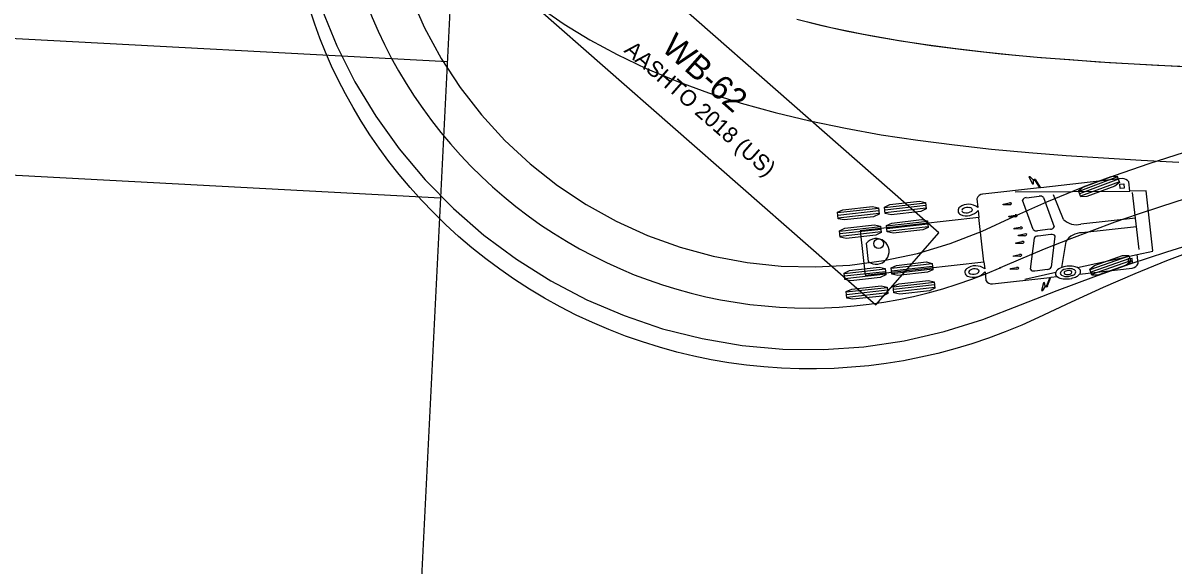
# Model space of a CAD drawing. Extents: x 260275 to 261282, y 610916 to 614143.
# Drawn here: x 260983.2 to 261085.2, y 611559.8 to 611607.9 of the extents above; entities that cross this region are included whole.
import ezdxf

# ---------------------------------------------------------------- set-up
doc = ezdxf.new("R2010")
doc.units = 0
for name, color, linetype in [('DR_P_Ditch', 7, 'Continuous'), ('GE_X_Alignment', 7, 'Continuous'), ('UT_X_Water_Cells', 7, 'Continuous')]:
    doc.layers.add(name, color=color, linetype=linetype)

msp = doc.modelspace()

# ---------------------------------------------------------------- linework, layer by layer
at = {"layer": 'DR_P_Ditch'}
for p, q in [((260829.51, 611614.68), (261020.82, 611604.53)), ((260828.86, 611602.6), (261020.18, 611592.44))]:
    msp.add_line(p, q, dxfattribs=at)
at = {"layer": 'GE_X_Alignment'}
msp.add_line((260986.25, 610915.95), (261148.28, 614142.84), dxfattribs=at)
at = {"layer": 'UT_X_Water_Cells'}
for p, q in [((261072.76, 611594.02), (261072.75, 611594.03)), ((261072.77, 611593.99), (261072.76, 611594.02)), ((261080.22, 611594.28), (261076.79, 611593)), ((261080.31, 611594.07), (261076.87, 611592.78)), ((261071.14, 611592.97), (261081.33, 611593.03)), ((261080.39, 611593.85), (261076.95, 611592.57)), ((261080.43, 611593.63), (261080.78, 611593.67)), ((261080.47, 611593.25), (261080.43, 611593.63)), ((261080.82, 611593.29), (261080.47, 611593.25)), ((261080.78, 611593.67), (261080.82, 611593.29)), ((261082.14, 611587.84), (261081.57, 611592.91)), ((261083.36, 611587.71), (261082.77, 611593.04)), ((261063.2, 611591.96), (261059.56, 611591.55)), ((261067.75, 611592.34), (261067.84, 611591.57)), ((261070.09, 611591.87), (261070.64, 611591.97)), ((261070.1, 611591.79), (261070.09, 611591.87)), ((261072.75, 611589.62), (261071.81, 611592.22)), ((261072.16, 611592.44), (261073.28, 611592.57)), ((261073.67, 611592.46), (261074.61, 611589.85)), ((261075.43, 611590.51), (261074.55, 611592.69)), ((261059.03, 611591.49), (261055.38, 611591.08)), ((261059.05, 611591.26), (261055.41, 611590.86)), ((261059.08, 611591.04), (261055.43, 611590.63)), ((261063.23, 611591.73), (261059.58, 611591.32)), ((261063.25, 611591.5), (261059.61, 611591.09)), ((261070.65, 611591.81), (261070.1, 611591.79)), ((261070.6, 611590.8), (261071.17, 611590.9)), ((261059.21, 611589.85), (261055.57, 611589.44)), ((261063.38, 611590.32), (261059.74, 611589.91)), ((261063.41, 611590.09), (261059.77, 611589.68)), ((261063.43, 611589.86), (261059.79, 611589.45)), ((261068.38, 611586.74), (261067.94, 611590.69)), ((261070.61, 611590.72), (261070.6, 611590.8)), ((261071.18, 611590.75), (261070.61, 611590.72)), ((261071.06, 611589.73), (261071.6, 611589.83)), ((261081.83, 611590.62), (261076.97, 611590.08)), ((261081.91, 611589.86), (261077.05, 611589.32)), ((261059.24, 611589.62), (261055.59, 611589.22)), ((261059.26, 611589.4), (261055.62, 611588.99)), ((261071.07, 611589.65), (261071.06, 611589.73)), ((261071.62, 611589.67), (261071.07, 611589.65)), ((261071.43, 611589.12), (261071.98, 611589.22)), ((261071.44, 611589.04), (261071.43, 611589.12)), ((261071.99, 611589.06), (261071.44, 611589.04)), ((261072.84, 611588.84), (261072.49, 611586.09)), ((261074.26, 611589.63), (261073.14, 611589.51)), ((261074.31, 611589.16), (261073.19, 611589.03)), ((261074.36, 611586.27), (261074.7, 611589.02)), ((261057.93, 611588.39), (261058.11, 611586.78)), ((261071.2, 611588.44), (261071.74, 611588.54)), ((261071.21, 611588.36), (261071.2, 611588.44)), ((261071.76, 611588.38), (261071.21, 611588.36)), ((261075.65, 611588.56), (261075.27, 611586.23)), ((261070.99, 611587.29), (261071.53, 611587.39)), ((261071, 611587.21), (261070.99, 611587.29)), ((261071.55, 611587.24), (261071, 611587.21)), ((261076.67, 611586.24), (261081.96, 611587.4)), ((261081.24, 611587.26), (261077.78, 611586.04)), ((261081.31, 611587.05), (261077.86, 611585.82)), ((261081.39, 611586.83), (261077.93, 611585.61)), ((261081.52, 611587.04), (261081.17, 611587)), ((261081.17, 611587), (261081.21, 611586.62)), ((261081.56, 611586.66), (261081.52, 611587.04)), ((261059.63, 611586.09), (261055.98, 611585.68)), ((261059.65, 611585.86), (261056.01, 611585.46)), ((261063.8, 611586.56), (261060.16, 611586.15)), ((261063.83, 611586.33), (261060.18, 611585.92)), ((261063.85, 611586.1), (261060.21, 611585.69)), ((261068.48, 611585.86), (261068.56, 611585.09)), ((261070.73, 611586.14), (261071.27, 611586.24)), ((261070.74, 611586.06), (261070.73, 611586.14)), ((261071.29, 611586.08), (261070.74, 611586.06)), ((261072.01, 611585.22), (261074.75, 611585.82)), ((261072.88, 611585.95), (261074.01, 611586.08)), ((261076.86, 611585.66), (261081.54, 611586.18)), ((261081.21, 611586.62), (261081.56, 611586.66)), ((261059.68, 611585.64), (261056.04, 611585.23)), ((261063.99, 611584.92), (261060.34, 611584.51)), ((261059.81, 611584.45), (261056.17, 611584.04)), ((261059.84, 611584.22), (261056.19, 611583.82)), ((261059.86, 611584), (261056.22, 611583.59)), ((261064.01, 611584.69), (261060.37, 611584.28)), ((261064.04, 611584.46), (261060.39, 611584.05)), ((261073.82, 611584.55), (261073.8, 611584.53)), ((261073.81, 611584.58), (261073.82, 611584.55))]:
    msp.add_line(p, q, dxfattribs=at)
for points in [[(261022.79, 611614.58), (261022.78, 611614.56), (261058.78, 611582.93), (261061.59, 611586.12), (261064.39, 611589.32), (261028.39, 611620.95), (261028.37, 611620.93)], [(261017.52, 611610.37), (261018.77, 611607.52), (261020.25, 611604.8), (261021.93, 611602.22), (261023.82, 611599.78), (261025.9, 611597.52), (261028.15, 611595.43), (261030.55, 611593.53), (261033.1, 611591.84), (261035.77, 611590.36), (261038.55, 611589.09), (261041.43, 611588.06), (261044.37, 611587.26), (261047.37, 611586.69), (261050.4, 611586.37), (261053.44, 611586.29), (261056.48, 611586.45), (261059.5, 611586.85), (261062.48, 611587.49), (261065.39, 611588.37), (261068.23, 611589.47), (261071.04, 611590.78), (261073.95, 611592.07), (261076.92, 611593.28), (261079.95, 611594.41), (261083.03, 611595.47), (261086.16, 611596.47)], [(261029.01, 611609.32), (261031.15, 611607.85), (261033.43, 611606.45), (261035.86, 611605.14), (261038.43, 611603.92), (261041.13, 611602.79), (261043.95, 611601.76), (261046.86, 611600.83), (261049.87, 611599.99), (261052.95, 611599.25), (261056.09, 611598.6), (261059.28, 611598.03), (261062.51, 611597.54), (261065.77, 611597.12), (261069.06, 611596.76), (261072.36, 611596.45), (261075.67, 611596.19), (261078.99, 611595.97), (261082.33, 611595.77), (261085.66, 611595.6)], [(261087.32, 611587.86), (261084.56, 611586.82), (261081.77, 611585.69), (261078.96, 611584.47), (261076.11, 611583.17), (261073.21, 611581.79), (261071.74, 611581.13), (261070.27, 611580.52), (261068.79, 611579.97), (261067.3, 611579.46), (261065.8, 611579.01), (261064.29, 611578.62), (261062.77, 611578.27), (261061.25, 611577.97), (261059.72, 611577.72), (261058.18, 611577.52), (261056.64, 611577.38), (261055.09, 611577.28), (261053.53, 611577.24), (261051.98, 611577.24), (261050.42, 611577.3), (261048.86, 611577.41), (261047.31, 611577.57), (261045.75, 611577.78), (261044.2, 611578.05), (261042.66, 611578.37), (261041.13, 611578.73), (261039.6, 611579.16), (261038.09, 611579.63), (261036.6, 611580.15), (261035.12, 611580.73), (261033.66, 611581.35), (261032.22, 611582.02), (261030.81, 611582.74), (261029.42, 611583.51), (261028.07, 611584.32), (261026.74, 611585.18), (261025.45, 611586.08), (261024.19, 611587.01), (261022.97, 611587.99), (261021.79, 611589), (261020.65, 611590.04), (261019.55, 611591.11), (261018.5, 611592.21), (261017.49, 611593.34), (261016.53, 611594.49), (261015.61, 611595.65), (261014.75, 611596.83), (261013.92, 611598.03), (261013.15, 611599.24), (261012.43, 611600.45), (261011.75, 611601.67), (261011.12, 611602.89), (261010.53, 611604.12), (261009.99, 611605.36), (261009.49, 611606.59), (261009.03, 611607.83), (261008.61, 611609.07)], [(261009.66, 611609.18), (261011, 611605.91), (261012.6, 611602.73), (261014.44, 611599.68), (261016.52, 611596.78), (261018.82, 611594.03), (261021.33, 611591.47), (261024.03, 611589.11), (261026.92, 611586.97), (261029.96, 611585.05), (261033.15, 611583.38), (261036.46, 611581.97), (261039.88, 611580.81), (261043.38, 611579.93), (261046.93, 611579.32), (261050.53, 611579), (261054.14, 611578.96), (261057.74, 611579.21), (261061.32, 611579.74), (261064.84, 611580.55), (261068.28, 611581.64), (261071.61, 611582.94), (261074.87, 611584.21), (261078.12, 611585.42), (261081.35, 611586.57), (261084.59, 611587.64), (261087.81, 611588.65)], [(261051.78, 611608.28), (261054, 611607.73), (261056.28, 611607.23), (261058.62, 611606.77), (261061, 611606.36), (261063.42, 611606), (261065.88, 611605.67), (261068.37, 611605.38), (261070.88, 611605.12), (261073.42, 611604.89), (261075.99, 611604.69), (261078.57, 611604.51), (261083.78, 611604.21), (261089.04, 611603.96)], [(261052.01, 611608.22), (261054.81, 611607.54), (261057.7, 611606.94), (261060.67, 611606.42), (261063.7, 611605.96), (261066.78, 611605.56), (261069.92, 611605.21), (261073.09, 611604.92), (261076.29, 611604.67), (261079.53, 611604.45), (261082.79, 611604.26), (261086.07, 611604.09)], [(261072.89, 611593.99), (261072.89, 611593.99), (261073.32, 611593.31), (261068.27, 611592.75)], [(261072.83, 611594.04), (261072.75, 611594.03), (261072.47, 611594.3), (261072.35, 611594.29), (261072.68, 611593.66), (261072.79, 611593.67), (261072.77, 611593.99), (261072.85, 611594)], [(261080.65, 611594.13), (261073.42, 611593.32), (261072.97, 611594.02)], [(261083.36, 611587.71), (261082.77, 611593.04), (261081.33, 611593.03), (261081.24, 611593.84)], [(261067.87, 611591.31), (261067.94, 611590.69), (261057.4, 611589.51), (261057.84, 611585.57), (261068.38, 611586.74), (261068.45, 611586.11)], [(261082.05, 611586.59), (261081.96, 611587.4), (261083.35, 611587.7)], [(261069.15, 611584.8), (261074.21, 611585.36), (261073.93, 611584.61), (261073.93, 611584.61)], [(261073.9, 611584.59), (261073.81, 611584.58), (261073.76, 611584.9), (261073.66, 611584.89), (261073.48, 611584.2), (261073.6, 611584.21), (261073.8, 611584.53), (261073.89, 611584.54)], [(261074.02, 611584.6), (261074.3, 611585.37), (261074.87, 611585.44)]]:
    msp.add_lwpolyline(points, dxfattribs=at)
for points in [[(261080.21, 611594.34), (261080.41, 611593.8), (261079.98, 611593.46), (261077.51, 611592.53), (261076.97, 611592.51), (261076.77, 611593.05), (261077.19, 611593.39), (261079.66, 611594.32)], [(261063.2, 611592.01), (261063.26, 611591.44), (261062.77, 611591.22), (261060.14, 611590.92), (261059.61, 611591.04), (261059.55, 611591.61), (261060.04, 611591.83), (261062.67, 611592.13)], [(261059.02, 611591.55), (261059.08, 611590.98), (261058.59, 611590.75), (261055.97, 611590.46), (261055.44, 611590.57), (261055.38, 611591.14), (261055.87, 611591.37), (261058.49, 611591.66)], [(261059.2, 611589.91), (261059.27, 611589.34), (261058.78, 611589.11), (261056.15, 611588.82), (261055.62, 611588.93), (261055.56, 611589.5), (261056.05, 611589.73), (261058.67, 611590.02)], [(261063.38, 611590.37), (261063.44, 611589.8), (261062.95, 611589.58), (261060.33, 611589.28), (261059.8, 611589.4), (261059.73, 611589.97), (261060.22, 611590.19), (261062.85, 611590.49)], [(261081.22, 611587.32), (261081.41, 611586.78), (261080.98, 611586.44), (261078.49, 611585.56), (261077.95, 611585.55), (261077.76, 611586.09), (261078.19, 611586.43), (261080.68, 611587.31)], [(261059.62, 611586.15), (261059.69, 611585.58), (261059.19, 611585.35), (261056.57, 611585.06), (261056.04, 611585.17), (261055.98, 611585.74), (261056.47, 611585.97), (261059.09, 611586.26)], [(261063.8, 611586.61), (261063.86, 611586.04), (261063.37, 611585.82), (261060.75, 611585.52), (261060.22, 611585.64), (261060.15, 611586.21), (261060.64, 611586.43), (261063.27, 611586.73)], [(261063.98, 611584.97), (261064.04, 611584.4), (261063.55, 611584.18), (261060.93, 611583.88), (261060.4, 611584), (261060.34, 611584.57), (261060.83, 611584.79), (261063.45, 611585.09)], [(261059.81, 611584.51), (261059.87, 611583.94), (261059.38, 611583.71), (261056.75, 611583.42), (261056.22, 611583.53), (261056.16, 611584.1), (261056.65, 611584.33), (261059.28, 611584.62)]]:
    msp.add_lwpolyline(points, close=True, dxfattribs=at)
for centre, radius in [((261059.04, 611588.36), 0.424), ((261069.82, 611586.21), 0.0417), ((261069.82, 611586.21), 0.0417)]:
    msp.add_circle(centre, radius, dxfattribs=at)
for centre, radius, start, end in [((261052.87, 611624.64), 42, 177.1255, 293.7992), ((261130.35, 611448.96), 150, 87.0825, 113.7992), ((261072.91, 611593.94), 0.127, 64.2517, 128.4608), ((261072.89, 611594.1), 0.11, 249.3037, 269.4121), ((261072.96, 611594.04), 0.0244, 307.2238, 60.5382), ((261080.63, 611593.34), 0.792, 39.6673, 88.8228), ((261068.3, 611592.18), 0.571, 93.2716, 163.6632), ((261070.7, 611591.79), 0.192, 41.4319, 108.9065), ((261070.67, 611592.01), 0.192, 263.7786, 331.3079), ((261072.12, 611592.11), 0.334, 87.4934, 160.0914), ((261073.38, 611592.18), 0.403, 44.3559, 103.8139), ((261066.47, 611591.29), 0.387, 127.8518, 244.8607), ((261067.02, 611590.51), 1.34, 52.3917, 125.9465), ((261066.83, 611592.17), 1.34, 246.766, 320.3208), ((261066.65, 611591.27), 0.228, 113.6585, 175.5534), ((261066.66, 611591.37), 0.262, 200.1482, 266.6734), ((261066.96, 611590.71), 0.86, 77.9222, 117.8916), ((261066.81, 611591.98), 0.879, 259.2241, 293.8194), ((261067.09, 611591.27), 0.29, 24.0005, 80.1605), ((261067.11, 611591.41), 0.247, 284.7598, 354.6389), ((261071.2, 611590.72), 0.192, 41.4319, 108.9065), ((261071.18, 611590.94), 0.192, 263.7786, 331.3079), ((261071.66, 611589.64), 0.192, 41.4319, 108.9065), ((261074.29, 611589.98), 0.342, 267.958, 337.8845), ((261076.58, 611591.67), 1.63, 225.0321, 283.6228), ((261058.83, 611587.67), 1.14, 231.3562, 141.3562), ((261071.64, 611589.86), 0.192, 263.7786, 331.3079), ((261072.04, 611589.03), 0.192, 41.4319, 108.9065), ((261072.01, 611589.25), 0.192, 263.806, 331.2805), ((261073.04, 611589.89), 0.397, 224.1174, 282.2804), ((261073.18, 611588.64), 0.397, 90.4321, 148.5951), ((261074.42, 611588.83), 0.342, 34.8279, 104.7544), ((261077.03, 611587.69), 1.63, 89.0897, 147.6804), ((261071.8, 611588.36), 0.192, 41.4046, 108.9338), ((261071.78, 611588.58), 0.192, 263.806, 331.2805), ((261071.6, 611587.21), 0.192, 41.4046, 108.9338), ((261071.57, 611587.43), 0.192, 263.806, 331.2805), ((261067.07, 611585.83), 0.383, 126.827, 245.8855), ((261067.63, 611585.05), 1.34, 52.3917, 125.9465), ((261067.44, 611586.71), 1.34, 246.766, 320.3208), ((261067.29, 611585.79), 0.262, 106.0391, 172.5643), ((261067.24, 611585.89), 0.228, 197.1591, 259.0539), ((261067.56, 611585.24), 0.879, 78.8931, 113.4883), ((261067.72, 611585.85), 0.247, 18.0735, 87.9526), ((261067.68, 611585.99), 0.29, 292.5519, 348.712), ((261071.34, 611586.06), 0.192, 41.4046, 108.9338), ((261071.31, 611586.28), 0.192, 263.806, 331.2805), ((261072.78, 611586.27), 0.334, 212.6211, 285.2191), ((261074.01, 611586.48), 0.403, 268.8986, 328.3565), ((261075.02, 611585.7), 0.301, 156.5875, 240.4858), ((261075.45, 611585.44), 0.799, 112.1557, 151.4233), ((261075.99, 611584.35), 2.01, 95.9976, 114.6805), ((261075.35, 611585.74), 0.199, 140.1595, 240.7988), ((261075.85, 611585.22), 0.914, 93.1907, 135.2486), ((261075.61, 611585.77), 0.12, 111.3323, 256.8104), ((261075.89, 611585.35), 0.617, 88.6438, 121.8346), ((261076.01, 611584.31), 2.05, 80.7373, 96.6626), ((261075.94, 611585.04), 1.1, 69.622, 97.5146), ((261075.95, 611585.71), 0.27, 27.5052, 100.249), ((261075.97, 611585.87), 0.22, 287.3661, 349.0644), ((261076.12, 611585.93), 0.407, 287.5869, 350.3913), ((261076.26, 611585.81), 0.268, 11.4289, 75.1065), ((261076.2, 611585.27), 1.07, 57.8128, 82.0817), ((261076.58, 611585.85), 0.38, 9.6866, 60.2101), ((261076.63, 611585.88), 0.328, 316.4446, 5.3489), ((261081.35, 611586.95), 0.792, 283.8897, 333.0451), ((261067.43, 611586.5), 0.86, 254.8209, 294.7903), ((261069.06, 611585.36), 0.571, 209.0493, 279.4408), ((261075.45, 611586.16), 0.924, 231.2533, 267.5315), ((261075.72, 611586.35), 0.913, 239.6659, 279.9261), ((261075.66, 611587.42), 2.2, 263.5553, 283.1905), ((261075.79, 611586.24), 0.631, 250.1645, 292.965), ((261075.75, 611586.68), 1.23, 275.9859, 293.5681), ((261075.78, 611586.97), 1.73, 282.7413, 297.9391), ((261076.29, 611586.09), 0.719, 294.8866, 323.1436), ((261073.95, 611584.66), 0.127, 244.2517, 308.4608), ((261073.96, 611584.5), 0.11, 103.3004, 123.4087), ((261074.01, 611584.58), 0.0244, 312.1743, 65.4886)]:
    msp.add_arc(centre, radius, start, end, dxfattribs=at)
for centre, major_axis, start_param, end_param in [((261072.9, 611594.03), (-0.0777, -0.0087), 5.756759, 7.026061), ((261072.9, 611594.03), (0.0777, 0.0087), 4.442794, 5.713538), ((261073.96, 611584.57), (0.0777, 0.0087), 2.398717, 3.668019), ((261073.96, 611584.57), (-0.0777, -0.0087), 3.71124, 4.981984)]:
    msp.add_ellipse(centre, major_axis=major_axis, ratio=0.5, start_param=start_param, end_param=end_param, dxfattribs=at)

# ---------------------------------------------------------------- texts
for s, height, p in [('WB-62', 2.125, (261039.68, 611605.6)), ('AASHTO 2018 (US)', 1.4167, (261036.39, 611605.42))]:
    msp.add_text(s, height=height, rotation=318.6977, dxfattribs=at).set_placement(p)

doc.saveas('drawing.dxf')
